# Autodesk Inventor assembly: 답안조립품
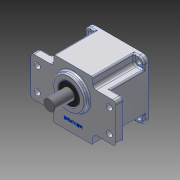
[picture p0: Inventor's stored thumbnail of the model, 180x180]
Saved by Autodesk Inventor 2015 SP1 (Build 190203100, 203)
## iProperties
Created: 2014-12
Part Number: 답안조립품
Document SubType Name: Assembly
Designer: kjc
Author: kjc
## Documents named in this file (12)
- C:\Users\kjc\Desktop\Inventor2급-김재철\답안조립품.iam
- C:\Users\kjc\Desktop\Inventor2급-김재철\본체.ipt
- C:\Users\kjc\Desktop\Inventor2급-김재철\커버.ipt
- C:\Users\kjc\Desktop\Inventor2급-김재철\메인축.ipt
- C:\Users\kjc\Desktop\Inventor2급-김재철\서브축.ipt
- C:\Users\kjc\Desktop\Inventor2급-김재철\베어링 608.ipt
- 베어링 608.ipt
- C:\Users\kjc\Desktop\Inventor2급-김재철\베어링 6003.ipt
- 베어링 6003.ipt
- C:\Users\kjc\Desktop\Inventor2급-김재철\오일실 17x32x8.ipt
- C:\Users\kjc\Desktop\Inventor2급-김재철\오일실 8x22x7.ipt
- C:\Users\kjc\Desktop\Inventor2급-김재철\M4x0.5x16.ipt
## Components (4 placed, 1 different names)
1. M4x0.5x12:1
2. M4x0.5x12:2
3. M4x0.5x12:3
4. M4x0.5x12:4
